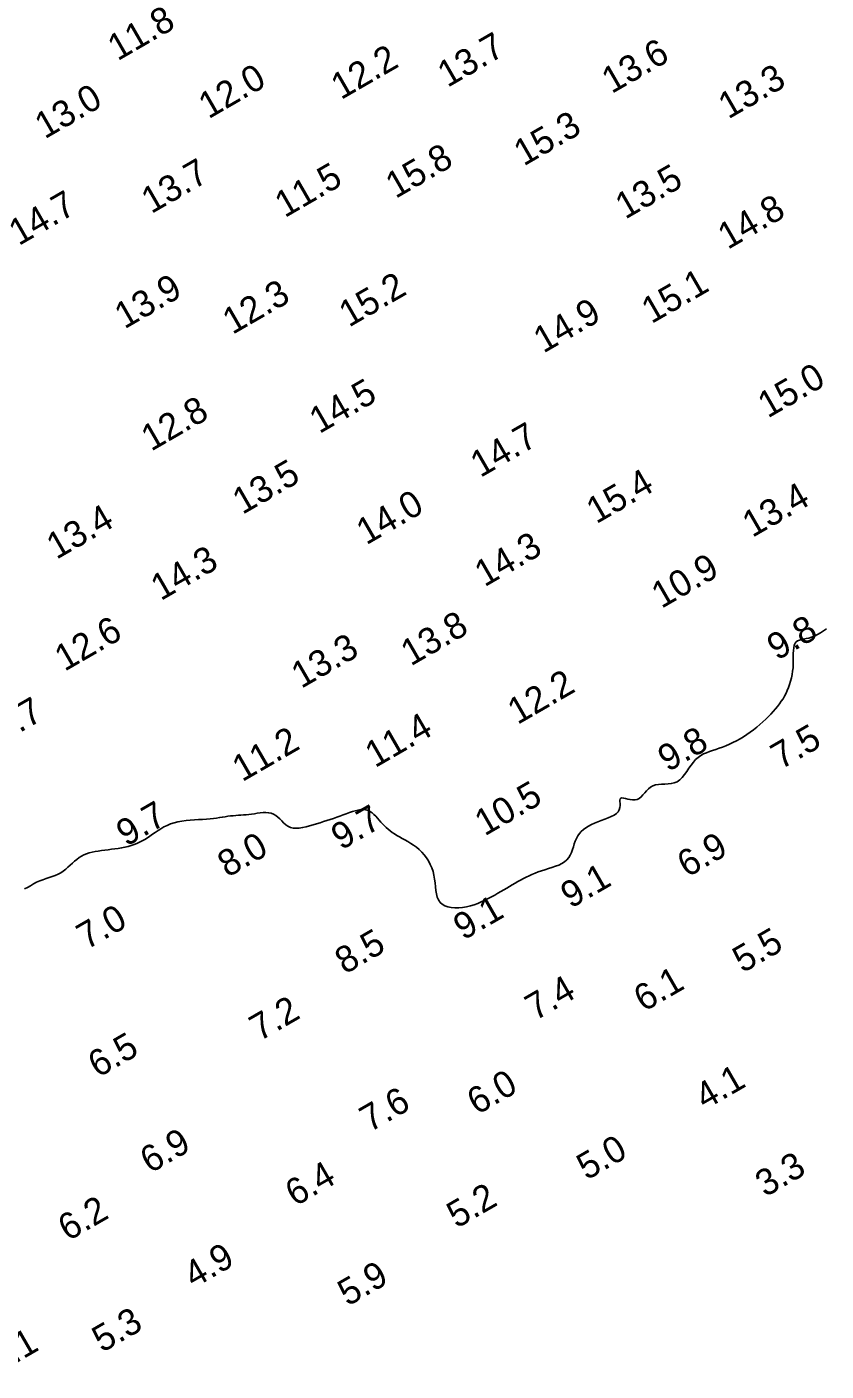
# Model space of a CAD drawing. Extents: x 3024098 to 3056816, y 418252 to 509144.
# Drawn here: x 3034614.7 to 3034766.5, y 418778.2 to 419033.5 of the extents above; entities that cross this region are included whole.
import ezdxf

# ---------------------------------------------------------------- set-up
doc = ezdxf.new("R2010")
doc.units = 0
doc.layers.add('V-CHAN-CONT-EL10', color=7, linetype='Continuous')
doc.layers.add('V-TOPO-SOUN-0911', color=7, linetype='Continuous')

msp = doc.modelspace()

# ---------------------------------------------------------------- linework, layer by layer
at = {"layer": 'V-CHAN-CONT-EL10'}
msp.add_lwpolyline([(3034766.58, 418919.2), (3034766.02, 418918.8), (3034765.44, 418918.43), (3034764.86, 418918.1), (3034764.29, 418917.81), (3034763.73, 418917.58), (3034763.2, 418917.42), (3034762.7, 418917.31), (3034762.23, 418917.22), (3034761.8, 418917.14), (3034761.42, 418917.04), (3034761.09, 418916.9), (3034760.82, 418916.71), (3034760.6, 418916.43), (3034760.45, 418916.05), (3034760.36, 418915.59), (3034760.3, 418915.06), (3034760.27, 418914.47), (3034760.26, 418913.83), (3034760.26, 418913.16), (3034760.24, 418912.48), (3034760.21, 418911.8), (3034760.14, 418911.13), (3034760.04, 418910.48), (3034759.91, 418909.85), (3034759.75, 418909.23), (3034759.57, 418908.62), (3034759.36, 418908.04), (3034759.13, 418907.48), (3034758.88, 418906.94), (3034758.6, 418906.41), (3034758.31, 418905.91), (3034757.99, 418905.42), (3034757.65, 418904.93), (3034757.28, 418904.45), (3034756.89, 418903.97), (3034756.46, 418903.49), (3034756.01, 418903), (3034755.53, 418902.51), (3034755.02, 418902), (3034754.48, 418901.49), (3034753.92, 418900.99), (3034753.33, 418900.49), (3034752.73, 418900.01), (3034752.1, 418899.54), (3034751.46, 418899.1), (3034750.81, 418898.68), (3034750.15, 418898.29), (3034749.48, 418897.92), (3034748.81, 418897.58), (3034748.13, 418897.27), (3034747.47, 418896.98), (3034746.81, 418896.72), (3034746.16, 418896.49), (3034745.53, 418896.28), (3034744.92, 418896.08), (3034744.33, 418895.88), (3034743.76, 418895.66), (3034743.21, 418895.42), (3034742.68, 418895.12), (3034742.19, 418894.77), (3034741.72, 418894.35), (3034741.28, 418893.85), (3034740.85, 418893.28), (3034740.44, 418892.69), (3034740.04, 418892.09), (3034739.62, 418891.5), (3034739.18, 418890.97), (3034738.71, 418890.51), (3034738.21, 418890.15), (3034737.66, 418889.91), (3034737.08, 418889.78), (3034736.47, 418889.71), (3034735.86, 418889.68), (3034735.25, 418889.66), (3034734.67, 418889.63), (3034734.12, 418889.54), (3034733.61, 418889.39), (3034733.17, 418889.13), (3034732.77, 418888.8), (3034732.4, 418888.42), (3034732.06, 418888.02), (3034731.72, 418887.63), (3034731.38, 418887.27), (3034731.02, 418886.98), (3034730.63, 418886.78), (3034730.2, 418886.69), (3034729.75, 418886.69), (3034729.28, 418886.75), (3034728.83, 418886.85), (3034728.41, 418886.96), (3034728.04, 418887.04), (3034727.73, 418887.08), (3034727.52, 418887.03), (3034727.39, 418886.89), (3034727.35, 418886.66), (3034727.34, 418886.36), (3034727.36, 418886.01), (3034727.36, 418885.62), (3034727.32, 418885.22), (3034727.21, 418884.83), (3034727, 418884.45), (3034726.66, 418884.12), (3034726.22, 418883.82), (3034725.69, 418883.54), (3034725.09, 418883.29), (3034724.46, 418883.04), (3034723.8, 418882.8), (3034723.14, 418882.55), (3034722.51, 418882.3), (3034721.91, 418882.03), (3034721.36, 418881.73), (3034720.86, 418881.41), (3034720.41, 418881.07), (3034720, 418880.7), (3034719.64, 418880.29), (3034719.33, 418879.86), (3034719.06, 418879.39), (3034718.85, 418878.88), (3034718.66, 418878.35), (3034718.49, 418877.8), (3034718.32, 418877.25), (3034718.13, 418876.72), (3034717.9, 418876.2), (3034717.61, 418875.73), (3034717.25, 418875.3), (3034716.81, 418874.92), (3034716.29, 418874.6), (3034715.71, 418874.32), (3034715.08, 418874.08), (3034714.43, 418873.85), (3034713.76, 418873.65), (3034713.09, 418873.44), (3034712.44, 418873.24), (3034711.81, 418873.02), (3034711.21, 418872.79), (3034710.63, 418872.54), (3034710.08, 418872.29), (3034709.53, 418872.03), (3034709, 418871.75), (3034708.48, 418871.47), (3034707.95, 418871.18), (3034707.43, 418870.88), (3034706.9, 418870.58), (3034706.37, 418870.27), (3034705.83, 418869.95), (3034705.27, 418869.63), (3034704.71, 418869.3), (3034704.14, 418868.97), (3034703.55, 418868.63), (3034702.94, 418868.29), (3034702.31, 418867.96), (3034701.67, 418867.63), (3034701.01, 418867.33), (3034700.34, 418867.04), (3034699.64, 418866.78), (3034698.94, 418866.56), (3034698.21, 418866.39), (3034697.47, 418866.26), (3034696.73, 418866.19), (3034696.01, 418866.18), (3034695.32, 418866.24), (3034694.68, 418866.37), (3034694.09, 418866.57), (3034693.59, 418866.86), (3034693.18, 418867.23), (3034692.87, 418867.7), (3034692.65, 418868.24), (3034692.5, 418868.85), (3034692.4, 418869.51), (3034692.32, 418870.21), (3034692.24, 418870.93), (3034692.15, 418871.66), (3034692.02, 418872.39), (3034691.84, 418873.1), (3034691.6, 418873.79), (3034691.3, 418874.45), (3034690.96, 418875.09), (3034690.58, 418875.69), (3034690.16, 418876.26), (3034689.7, 418876.78), (3034689.21, 418877.26), (3034688.7, 418877.7), (3034688.16, 418878.09), (3034687.62, 418878.44), (3034687.07, 418878.77), (3034686.52, 418879.08), (3034685.98, 418879.37), (3034685.46, 418879.65), (3034684.98, 418879.93), (3034684.52, 418880.22), (3034684.09, 418880.51), (3034683.69, 418880.81), (3034683.31, 418881.12), (3034682.95, 418881.44), (3034682.61, 418881.77), (3034682.27, 418882.12), (3034681.95, 418882.47), (3034681.62, 418882.84), (3034681.3, 418883.22), (3034680.97, 418883.58), (3034680.63, 418883.92), (3034680.27, 418884.22), (3034679.9, 418884.48), (3034679.5, 418884.69), (3034679.07, 418884.82), (3034678.61, 418884.87), (3034678.12, 418884.85), (3034677.61, 418884.77), (3034677.08, 418884.64), (3034676.52, 418884.47), (3034675.95, 418884.27), (3034675.37, 418884.05), (3034674.77, 418883.83), (3034674.17, 418883.61), (3034673.56, 418883.4), (3034672.94, 418883.18), (3034672.32, 418882.98), (3034671.68, 418882.77), (3034671.04, 418882.56), (3034670.39, 418882.35), (3034669.73, 418882.14), (3034669.06, 418881.94), (3034668.39, 418881.74), (3034667.72, 418881.57), (3034667.07, 418881.43), (3034666.44, 418881.34), (3034665.84, 418881.31), (3034665.28, 418881.35), (3034664.76, 418881.48), (3034664.29, 418881.7), (3034663.87, 418881.98), (3034663.47, 418882.33), (3034663.1, 418882.69), (3034662.73, 418883.07), (3034662.35, 418883.42), (3034661.96, 418883.73), (3034661.54, 418883.98), (3034661.09, 418884.15), (3034660.6, 418884.25), (3034660.09, 418884.28), (3034659.56, 418884.27), (3034659.02, 418884.22), (3034658.47, 418884.15), (3034657.92, 418884.07), (3034657.38, 418883.99), (3034656.86, 418883.93), (3034656.35, 418883.88), (3034655.85, 418883.84), (3034655.36, 418883.8), (3034654.87, 418883.77), (3034654.38, 418883.73), (3034653.89, 418883.69), (3034653.4, 418883.64), (3034652.9, 418883.57), (3034652.39, 418883.5), (3034651.86, 418883.42), (3034651.32, 418883.33), (3034650.74, 418883.25), (3034650.13, 418883.17), (3034649.49, 418883.09), (3034648.81, 418883.03), (3034648.08, 418882.98), (3034647.32, 418882.94), (3034646.53, 418882.9), (3034645.73, 418882.84), (3034644.94, 418882.77), (3034644.15, 418882.67), (3034643.39, 418882.53), (3034642.67, 418882.35), (3034641.98, 418882.12), (3034641.35, 418881.85), (3034640.74, 418881.55), (3034640.17, 418881.22), (3034639.62, 418880.87), (3034639.1, 418880.52), (3034638.59, 418880.17), (3034638.09, 418879.83), (3034637.59, 418879.5), (3034637.1, 418879.2), (3034636.6, 418878.91), (3034636.1, 418878.65), (3034635.59, 418878.41), (3034635.06, 418878.2), (3034634.51, 418878.01), (3034633.93, 418877.84), (3034633.33, 418877.7), (3034632.71, 418877.58), (3034632.07, 418877.48), (3034631.43, 418877.39), (3034630.77, 418877.31), (3034630.13, 418877.23), (3034629.49, 418877.15), (3034628.86, 418877.07), (3034628.26, 418876.98), (3034627.68, 418876.88), (3034627.11, 418876.75), (3034626.57, 418876.61), (3034626.05, 418876.44), (3034625.55, 418876.23), (3034625.08, 418876), (3034624.62, 418875.72), (3034624.18, 418875.4), (3034623.76, 418875.04), (3034623.35, 418874.67), (3034622.93, 418874.28), (3034622.51, 418873.9), (3034622.08, 418873.52), (3034621.62, 418873.17), (3034621.14, 418872.86), (3034620.63, 418872.59), (3034620.09, 418872.36), (3034619.52, 418872.15), (3034618.94, 418871.95), (3034618.35, 418871.75), (3034617.75, 418871.54), (3034617.15, 418871.31), (3034616.56, 418871.04), (3034615.97, 418870.73), (3034615.4, 418870.4), (3034614.84, 418870.07), (3034614.29, 418869.77)], dxfattribs=at)

# ---------------------------------------------------------------- texts
at = {"layer": 'V-TOPO-SOUN-0911'}
for s, p in [('11.8 ', (3034631.94, 419026.94)), ('13.7 ', (3034694.6, 419021.89)), ('13.6 ', (3034725.77, 419020.71)), ('12.2 ', (3034674.36, 419019.56)), ('12.0 ', (3034649.21, 419015.92)), ('13.3 ', (3034747.92, 419015.89)), ('13.0 ', (3034618.11, 419012.11)), ('15.3 ', (3034709.07, 419006.96)), ('15.8 ', (3034684.73, 419000.79)), ('13.7 ', (3034638.34, 418997.91)), ('11.5 ', (3034663.69, 418997.15)), ('13.5 ', (3034728.35, 418996.86)), ('14.7 ', (3034613.17, 418991.84)), ('14.8 ', (3034747.82, 418991.12)), ('15.1 ', (3034733.33, 418977.02)), ('13.9 ', (3034633.25, 418976.02)), ('12.3 ', (3034653.76, 418974.97)), ('15.2 ', (3034675.87, 418976.35)), ('14.9 ', (3034712.81, 418971.43)), ('15.0 ', (3034755.42, 418959.09)), ('14.5 ', (3034670.25, 418956.14)), ('12.8 ', (3034638.31, 418952.8)), ('14.7 ', (3034700.84, 418947.81)), ('13.5 ', (3034655.65, 418940.79)), ('15.4 ', (3034722.85, 418939.02)), ('13.4 ', (3034752.48, 418936.42)), ('14.0 ', (3034679.17, 418935.01)), ('13.4 ', (3034620.33, 418932.26)), ('14.3 ', (3034701.63, 418927.04)), ('14.3 ', (3034640.14, 418924.42)), ('10.9 ', (3034735.22, 418922.94)), ('12.6 ', (3034621.87, 418911)), ('13.8 ', (3034687.62, 418912.01)), ('9.8', (3034757.17, 418913.07)), ('13.3 ', (3034666.82, 418907.75)), ('12.2 ', (3034707.89, 418900.89)), ('11.7 ', (3034606.88, 418895.64)), ('11.4 ', (3034680.83, 418892.69)), ('11.2 ', (3034655.6, 418890.03)), ('9.8', (3034736.43, 418891.91)), ('7.5', (3034757.88, 418892.37)), ('10.5 ', (3034701.65, 418879.73)), ('9.7', (3034633.58, 418877.74)), ('9.7', (3034674.39, 418877.05)), ('8.0', (3034652.82, 418871.86)), ('6.9', (3034740.11, 418871.86)), ('9.1', (3034717.98, 418865.97)), ('9.1', (3034697.6, 418859.94)), ('7.0', (3034626.05, 418858.15)), ('8.5', (3034675.11, 418853.49)), ('5.5', (3034750.63, 418853.72)), ('6.1', (3034731.86, 418846.35)), ('7.4', (3034711.24, 418844.67)), ('7.2', (3034658.88, 418840.76)), ('6.5', (3034628.22, 418833.84)), ('6.0', (3034700.2, 418826.78)), ('4.1', (3034743.5, 418827.75)), ('7.6', (3034679.81, 418823.48)), ('6.9', (3034638.11, 418815.66)), ('5.0', (3034721.03, 418814.38)), ('3.3', (3034754.94, 418811.17)), ('6.4', (3034665.67, 418809.4)), ('5.2', (3034696.34, 418805.23)), ('6.2', (3034622.52, 418802.8)), ('4.9', (3034646.41, 418793.88)), ('5.9', (3034675.64, 418790.43)), ('5.3', (3034628.99, 418781.64)), ('5.1', (3034609.22, 418777.69))]:
    msp.add_text(s, height=5, rotation=30, dxfattribs=at).set_placement(p)

doc.saveas('drawing.dxf')
